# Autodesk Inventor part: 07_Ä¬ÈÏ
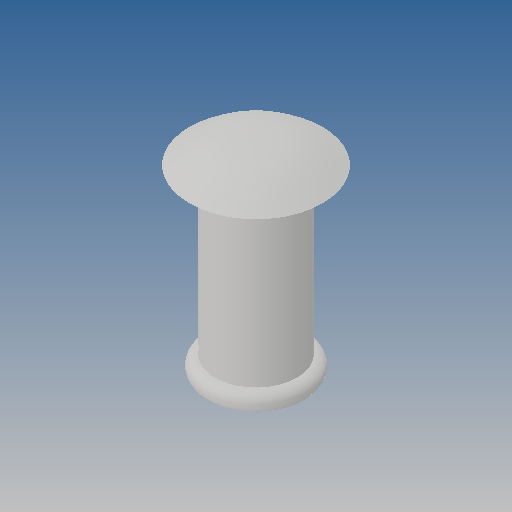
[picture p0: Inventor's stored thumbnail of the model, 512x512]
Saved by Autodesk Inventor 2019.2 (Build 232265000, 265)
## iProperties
Created: 2010-06
Part Number: 07_Ä¬ÈÏ
Material: Ogólny
Document SubType Name: Modeling
Designer: CADENGINEERING4
Density: 1 g/cm^3
Appearance: Domyślna
Author: CADENGINEERING4
Revision Number: ÈÎºÎ
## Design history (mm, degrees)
feature "NONE"
node "Bryła1"
